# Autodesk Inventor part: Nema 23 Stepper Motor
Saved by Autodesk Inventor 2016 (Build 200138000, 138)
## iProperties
Created: 2016-03
Part Number: Nema 23 Stepper Motor
Material: Generic
Document SubType Name: Modeling
Designer: bongo_000
Density: 1 g/cm^3
Appearance: Default
Author: bongo_000
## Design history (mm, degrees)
feature "CUT-EXTRUDE7"
body "Solid1"
